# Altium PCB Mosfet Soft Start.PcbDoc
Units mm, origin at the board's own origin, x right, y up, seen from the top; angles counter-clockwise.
Board outline 50.5 x 33.6 mm, 2 copper layers (Top Layer, Bottom Layer), stack 1.64 mm thick; 46 components, 22 nets, 109 pads, 85 vias.
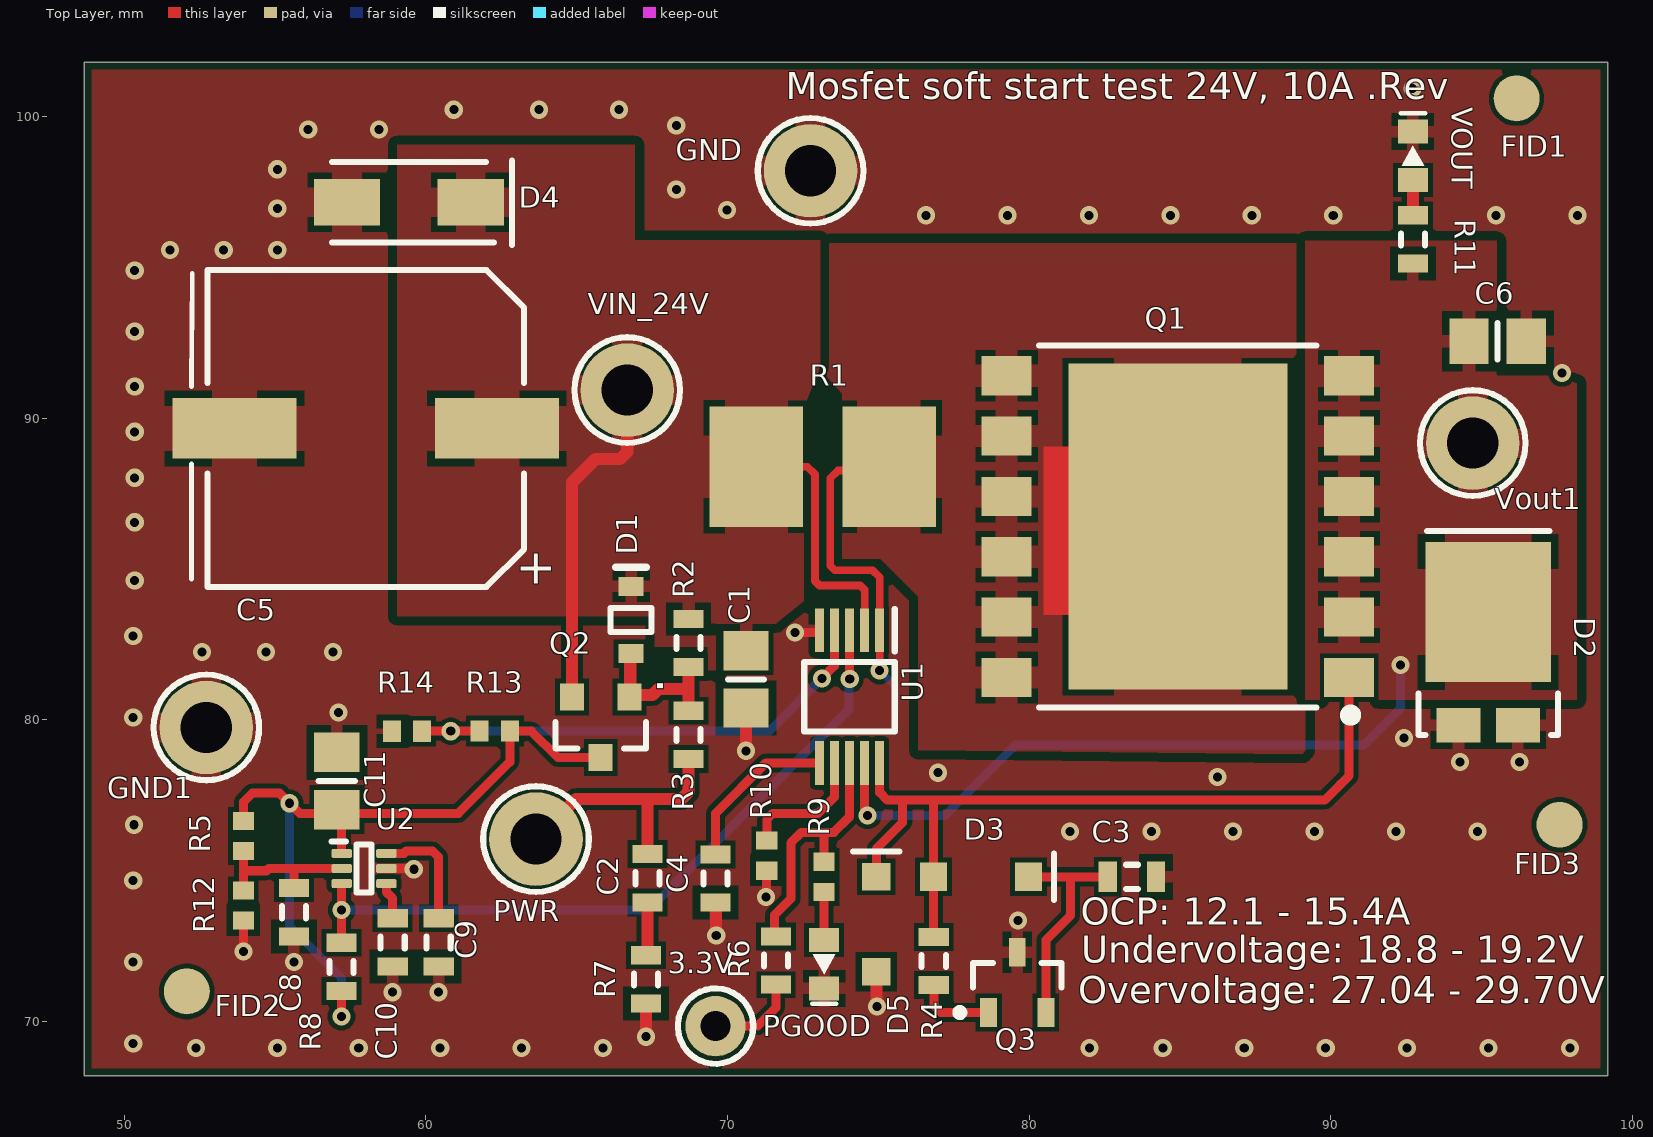
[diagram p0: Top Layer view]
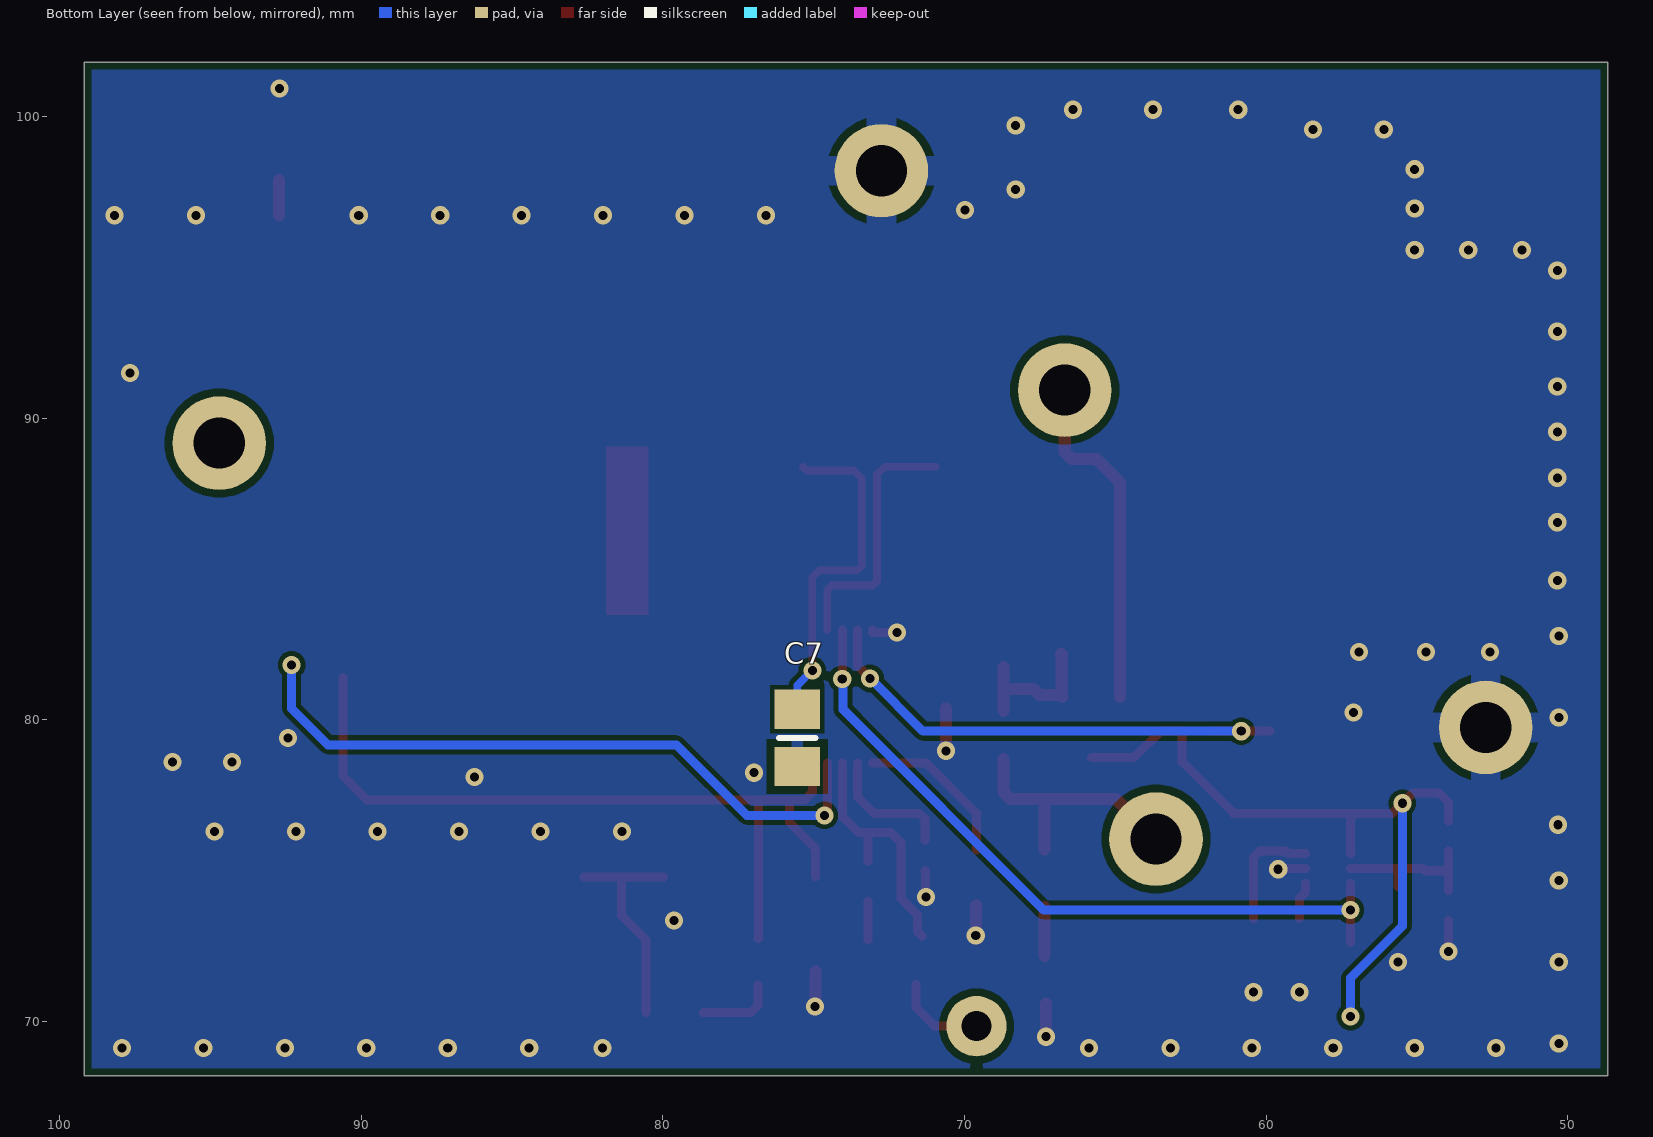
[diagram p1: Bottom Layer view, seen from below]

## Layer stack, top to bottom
Top Solder: solder mask 0.0102, Solder Resist, Dk 3.5
Top Layer: signal copper 0.07
Dielectric 1: dielectric 1.5, FR-4, Dk 4.8
Bottom Layer: signal copper 0.07
Bottom Solder: solder mask 0.0102, Solder Resist, Dk 3.5

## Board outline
48.675,68.2 99.175,68.2 99.175,101.8 48.675,101.8

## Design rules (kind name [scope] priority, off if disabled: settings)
BoardOutlineClearance [All] p1: gap=0.254 ignorepadtopadclearanceinfootprint=FALSE except(0: Arc-SplitContinuation Track-SplitContinuation SMDPad-SplitContinuation THPad-SplitContinuation Via-SplitContinuation Fill-SplitContinuation Poly-SplitContinuation Region-SplitContinuation Text-SplitContinuation; 0.05: Text-OutlineEdge)
Clearance "Clearance_MTG hole" [All vs (HasFootprint('M3 MOUNTING HOLE'))] p1: gap=0.152 ignorepadtopadclearanceinfootprint=TRUE except(0.25: THPad-Fill THPad-Poly THPad-Region Fill-Fill Fill-Poly Fill-Region Poly-Poly Poly-Region Region-Region; 0.4: SMDPad-Fill SMDPad-Poly SMDPad-Region)
Clearance [All] p2: gap=0.152 ignorepadtopadclearanceinfootprint=TRUE except(0.25: THPad-Fill THPad-Poly THPad-Region; 0.3: Fill-Fill Fill-Poly Fill-Region Poly-Poly Poly-Region Region-Region)
DiffPairsRouting DiffPairsRouting_1 [All] p1: maxlimit=0.254 minlimit=0.254 mostfreqgap=0.254 toplayer_minwidth=0.381 toplayer_maxwidth=0.381 toplayer_prefwidth=0.381 bottomlayer_minwidth=0.381 bottomlayer_maxwidth=0.381 bottomlayer_prefwidth=0.381 maxuncoupledlength=12.7
DiffPairsRouting [All] p2: maxlimit=0.254 minlimit=0.254 mostfreqgap=0.254 toplayer_minwidth=0.381 toplayer_maxwidth=0.381 toplayer_prefwidth=0.381 bottomlayer_minwidth=0.381 bottomlayer_maxwidth=0.381 bottomlayer_prefwidth=0.381 maxuncoupledlength=12.7
HoleSize [All] p1: absolutevalues=TRUE maxlimit=10 minlimit=0.2 maxpercent=80.000 minpercent=20.000
HoleToHoleClearance [All] p1: gap=0.3 allowstackedmicrovias=TRUE
MinimumSolderMaskSliver MinimumSolderMaskSliver_1 [All vs HasFootprint('FC2QFN')] p1: minsoldermaskwidth=0.01
MinimumSolderMaskSliver MinimumSolderMaskSliver_2 [All vs HasFootprint('DFN2020MD-6')] p2: minsoldermaskwidth=0.01
MinimumSolderMaskSliver [All] p3: minsoldermaskwidth=0.047
NetAntennae [All] p1: netantennaetolerance=0.8
PolygonConnect [All] p1: thpad.connectstyle=Relief thpad.reliefconductorwidth=0.6 thpad.reliefentries=4 thpad.polygonreliefangle="90 Angle" thpad.airgapwidth=0.2 smdpad.connectstyle=Relief smdpad.reliefconductorwidth=0.4 smdpad.reliefentries=4 smdpad.polygonreliefangle="90 Angle" smdpad.airgapwidth=0.2 via.connectstyle=Direct via.reliefconductorwidth=0.6 via.reliefentries=4 via.polygonreliefangle="90 Angle" via.airgapwidth=0.2
RoutingVias [All] p1: holewidth=0.2 width=0.45 viastyle="Through Hole" minholewidth=0.2 minwidth=0.4 maxholewidth=0.711 maxwidth=1.27
SilkToSilkClearance [All] p1: silktosilkclearance=0.01
SilkToSolderMaskClearance [IsPad] p1: minsilkscreentomaskgap=0.02 clearancetoexposedcopper=TRUE
SolderMaskExpansion [All] p1: expansion=0.102 istentingtop=FALSE
SupplyNets "Schematic Supply Nets" [InNet('+3.3V')] p1: voltage=0.000
SupplyNets "Schematic Supply Nets_9" [InNet('VIN_24V_SW')] p2: voltage=0.000
SupplyNets "Schematic Supply Nets_8" [InNet('Vin_24V')] p3: voltage=0.000
SupplyNets "Schematic Supply Nets_5" [InNet('GND')] p4: voltage=0.000
UnConnectedPin [All] p1 off:
UnRoutedNet [All] p1: checkbadconnections=TRUE
ViasUnderSMD [All] p1: allowed=FALSE
Width [All] p1: maxlimit=20 minlimit=0.152 preferedwidth=0.254
22 further rules are at their usual default settings.

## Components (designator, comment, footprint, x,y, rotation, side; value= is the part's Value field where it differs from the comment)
3.3V "TPAD6R" "TP - BLACK 1MM" 69.6,69.85 r0 top
C1 "1uF" 2012[0805] 70.612,81.341 r90 top
C2 "220nF" 1608(0603) 67.347,74.752 r270 top
C3 "3.3nF" 1608(0603) 83.4,74.8 r0 top
C4 "330nF" 1608(0603) 69.596,74.742 r270 top
C5 "100uF" FP-ZAG-MFG 58.007,89.662 r0 top
C6 "1uF" 2012[0805] 95.525,92.55 r180 top
C7 "1uF" 2012[0805] 75.541,79.404 r90 bottom
C8 "1nF" 1608(0603) 55.625,73.625 r270 top
C9 "0.33uF" 1608(0603) 60.425,72.625 r270 top
C10 "0.15uF" 1608(0603) 58.9,72.625 r270 top
C11 "1uF" 2012[0805] 57.05,77.975 r270 top
D1 "12V" SOD-323-3 66.802,83.312 r270 top value=24V
D2 "=Value" TO-277-3LD 95.21,82.575 r270 top
D3 "1N4148W-7-F" DIOD-SOD123-2_V 78.4,74.8 r0 top
D4 "24V" DIOM5127X229N 59.436,97.155 r180 top
D5 "36V" DIOD-SOD123-2_V 74.93,73.228 r90 top
FID1 "Fiducial" FID 96.15,100.6 r90 top
FID2 "Fiducial" FID 52.075,71 r90 top
FID3 "Fiducial" FID 97.575,76.525 r90 top
GND "TPAD6R" "TP - BLACK 1.5MM" 72.75,98.2 r0 top
GND1 "TPAD6R" "TP - BLACK 1.5MM" 52.725,79.75 r0 top
PGOOD "Power LED" "1608[0603]_LED Green" 73.2,71.9 r90 top value=Green
PWR "TPAD6R" "TP - BLACK 1.5MM" 63.65,76.05 r0 top
Q1 "PSMNR90-80ASEJ" CCPAK1212 84.923,86.407 r90 top
Q2 "" "FP-SOT23-MFG - PFET" 65.794,79.756 r270 top
Q3 "BJT NPN transistor" ONSC-SOT-23-3-318-08_V 79.6,71.3 r90 top
R1 "4mR" 2512_SENSE 73.152,88.392 r0 top
R2 "18K" 1608(0603) 68.707,82.55 r90 top
R3 "30K" 1608(0603) 68.707,79.502 r90 top
R4 "1K" 1608(0603) 76.835,72.009 r90 top
R5 "73.2K" 0402(1005) 53.95,76.15 r90 top
R6 "100K" 1608(0603) 71.6,72.025 r270 top
R7 "51R" 1608(0603) 67.3,71.4 r90 top
R8 "100K" 1608(0603) 57.2,71.815 r270 top
R9 "680R" 0402(1005) 73.2,74.8 r90 top
R10 "162K" 0402(1005) 71.3,75.5 r90 top
R11 "10K" 1608(0603) 92.712,95.925 r270 top
R12 "2.8K" 0402(1005) 53.95,73.85 r90 top
R13 "47.5K" 0402(1005) 62.284,79.629 r0 top
R14 "4.3K" 0402(1005) 59.375,79.625 r0 top
U1 "Soft start IC" VSSOP10 74.041,80.772 r270 top
U2 "Voltage supervisor. Resets for 1s when UVLO occurs" SOTFL50P160X60-6N 57.95,75.075 r0 top
VIN_24V "TPAD6R" "TP - BLACK 1.5MM" 66.675,90.932 r90 top
VOUT "Power LED" "1608[0603]_LED GREEN" 92.712,98.7 r270 top value=Green
Vout1 "TPAD6R" "TP - BLACK 1.5MM" 94.7,89.175 r90 top

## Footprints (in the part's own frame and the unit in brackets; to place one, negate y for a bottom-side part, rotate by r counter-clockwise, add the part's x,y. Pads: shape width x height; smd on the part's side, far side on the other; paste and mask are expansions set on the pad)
0402(1005) [mm] "Chip Resistor, Body 1.0x0.5mm, IPC Medium Density"
  rect 0.6x0.7 smd: 1(-0.5,0) 2(0.5,0)
  body extent -0.52,-0.27 0.53,0.28, height 0.4
1608(0603) [mm]
  rect 0.6x1 smd mask+0.076: 1(-0.8,0) 2(0.8,0)
  silkscreen extent -0.2,-0.4 0.2,0.4, body extent -0.8,-0.4 0.8,0.4, height 0.5
"1608[0603]_LED Green" [mm] "Chip Resistor; Body 1.1 x 0.8 mm (LxW)"
  rect 0.8x1 smd mask+0.076: A(0.8,0) K(-0.8,0)
  silkscreen extent -1.3,-0.4 0.33,0.4, body extent -0.81,-0.39 0.81,0.39, height 0.72
"1608[0603]_LED GREEN" [mm] "Chip Resistor; Body 1.1 x 0.8 mm (LxW)"
  rect 0.8x1 smd mask+0.076: A(0.8,0) K(-0.8,0)
  silkscreen extent -1.4,-0.39 0.33,0.41, body extent -0.81,-0.39 0.81,0.39, height 0.72
2012[0805] [mm]
  rect 1.3x1.5 smd: 1(-0.95,0) 2(0.95,0)
  silkscreen extent 0,-0.6 0,0.6, body extent -1.1,-0.7 1.1,0.7, height 0.6
2512_SENSE [mm] "Chip Resistor; Body 6.3 x 3.2 mm (LxW typ)"
  rect 3.1x4 smd: 1(-2.2,0) 2(2.2,0)
  body extent -3.22,-1.68 3.22,1.68, height 0.71
CCPAK1212 [mm]
  rect 1.3x1.65 smd paste-0.1: D(-5,5.675) D(-3,5.675) D(-1,5.675) D(1,5.675) D(3,5.675) D(5,5.675) G(-5,-5.675) S(-3,-5.675) S(-1,-5.675) S(1,-5.675) S(3,-5.675) S(5,-5.675)
  rect 10.8x7.26 smd paste-2539.97: D(0,0)
  silkscreen extent -6.3,-5.77 6,4.6, body extent -5.99,-6 6.01,6, height 2.5
DIOD-SOD123-2_V [mm] "SOD123, 2-Leads, Body 2.7x1.55mm, Height 1.45mm"
  rect 0.9x0.95 smd: A(-1.575,0) K(1.575,0)
  silkscreen extent 2.41,-0.77 2.41,0.77, body extent -1.35,-0.77 1.35,0.77, height 1.45
DIOM5127X229N [mm]
  rect 2.2x1.55 smd: 1(-2.05,0) 2(2.05,0)
  silkscreen extent -3.41,-1.38 2.55,1.42, body extent -2.61,-1.3 2.61,1.3, height 2.31
FID [mil]
  round 60 smd: 0(0,0)
"FP-SOT23-MFG - PFET" [mm]
  rect 0.9x0.8 smd paste+0: D(1,0) G(-1,0.95) S(-1,-0.95)
  silkscreen extent -0.18,-1.5 0.7,1.5, body extent -1.2,-1.45 1.2,1.45, height 1.1
FP-ZAG-MFG [mm]
  rect 4.1x2 smd paste+0 mask+0: +(4.35,0) -(-4.35,0)
  silkscreen extent -5.77,-5.25 5.25,5.25, body extent -6.65,-5.5 6.65,5.5, height 0.25
ONSC-SOT-23-3-318-08_V [mm] "SOT23, 3-Leads, Body 2.92x1.3mm, Pitch 0.95mm"
  rect 0.95x0.56 smd: 1(-1,0.95) 2(-1,-0.95) 3(1,0)
  silkscreen extent -1.12,-1.46 0.65,2.02, body extent -0.65,-1.46 0.65,1.46, height 1.11
SOD-323-3 [mm] "SOD, 2-Leads, Body 1.7x1.25mm"
  rect 0.63x0.83 smd: 1(-1.115,0) 2(1.115,0)
  silkscreen extent -1.75,-0.67 0.4,0.67, body extent -0.85,-0.63 0.85,0.63, height 1.06
SOTFL50P160X60-6N [mm]
  rrect33% 0.67x0.3 smd mask+0.05: 1(-0.74,0.5) 2(-0.74,0) 3(-0.74,-0.5) 4(0.74,-0.5) 5(0.74,0) 6(0.74,0.5)
  silkscreen extent -1.07,-0.8 0.25,0.9, body extent -0.8,-0.8 0.8,0.8, height 0.6
TO-277-3LD [mm]
  rect 1.15x1.45 smd paste+0 mask+0: A(2.75,0.985) A(2.75,-0.985)
  rect 4.65x4.15 smd paste+0 mask+0: K(-1,0)
  silkscreen extent -3.68,-2.31 3.08,2.31, body extent -3.42,-2.41 3.42,2.41, height 0.25
"TP - BLACK 1.5MM" [mm] "Test Point - Black - 1mm Hole"
  round 3.1 hole 1.7: 1(0,0)
  silkscreen extent -1.75,-1.75 1.75,1.75
"TP - BLACK 1MM" [mm] "Test Point - Black - 1mm Hole"
  round 2 hole 1: 1(0,0)
  silkscreen extent -1.25,-1.25 1.25,1.25
VSSOP10 [mm] "R-PDSO-G8, SOT765-1"
  rrect5% 1.45x0.3 smd: 1(-2.2,1) 2(-2.2,0.5) 3(-2.2,0) 4(-2.2,-0.5) 5(-2.2,-1) 6(2.2,-1) 7(2.2,-0.5) 8(2.2,0) 9(2.2,0.5) 10(2.2,1)
  silkscreen extent -2.9,-1.5 1.15,1.5, body extent -2.46,-1.5 2.46,1.5, height 1.11

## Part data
3.3V GND GND1 PWR VIN_24V Vout1: library part "Test Pad 0.6mm", "0.6mm round"
C1 C6 C7 C11: library part CAPNP, "CAP CER 1UF 100V X7S 0805", Case/Package=0805, Manufacturer="Murata Electronics", Manufacturer Part Number=GRJ21BC72A105KE11L, Rating=100V, Temperature Coefficient=X7S, Tolerance=±10%
C2 C4: library part CAPNP, "Multilayer Ceramic Capacitors MLCC - SMD/SMT SOFT 0603 50V 0.22uF X7R 10% AEC-Q200", Case/Package=0603, Manufacturer=KEMET, Manufacturer Part Number=CGA3E3X7R1H224K080AE, Rating=50V, Temperature Coefficient=X7R
C3: library part CAPNP, "CAP CER 3300PF 50V C0G/NP0 0603", Case/Package=0603, Manufacturer=KEMET, Manufacturer Part Number=C0603X332J5GACAUTO, Rating=50V, Temperature Coefficient="C0G, NP0"
C5: library part "CAP ALUM POLY HYB 100uF 50V SMD", "Cap Aluminum 100uF 50V 20% (10 X 10.2mm) SMD 0.028 Ohm 2000mA 5000 hr 105°C Embossed T/R", Case/Package=SMD, Manufacturer=Panasonic, Manufacturer Part Number=EEH-ZA1H101P, Rating=50V
C8: library part CAPNP, "CAP CER 0603 1NF 50V X7R 10%", Case/Package=0603, Manufacturer=KEMET, Manufacturer Part Number=C0603X102K5RAC3316, Rating=50V, Temperature Coefficient=X7R, Tolerance=±10%
C9: library part CAPNP, "CAP CER 0.33UF 25V X8R 0603", Case/Package=0603, Manufacturer="TDK Corporation", Manufacturer Part Number=C1608X8R1E334K080AE, Rating=25V, Temperature Coefficient=X7R, Tolerance=±10%
C10: library part CAPNP, "CAP CER 0.15UF 50V X7R 0603", Case/Package=0603, Manufacturer=KEMET, Manufacturer Part Number=C0603X154J5RECAUTO, Rating=50V, Temperature Coefficient=X7R, Tolerance=±5%
D1: library part SMA6J24A-Q, "TVS Diode (Uni-directional)", Case/Package=SOD-323F, Manufacturer=onsemi, Manufacturer Part Number=MM3Z12VB
D2: library part Schottky, "Schottky Diodes & Rectifiers 15A 50V Schottky Rectifier", Case/Package=TO-277-3, Manufacturer=onsemi, Manufacturer Part Number=FSV1550V, Rating=15A, Voltage - DC Reverse (Vr) (Max)=50V
D3: library part "D 100V 20A", "SURFACE-MOUNT FAST SWITCHING DIODE", Case/Package=SOD-123, Manufacturer=Diodes, Rating=300mA
D4: library part SMA6J24A-Q, "TVS Diode (Uni-directional)", Case/Package=DO-214AC-2, Manufacturer=Bourns
D5: library part SMA6J24A-Q, "TVS Diode (Uni-directional)", Case/Package=SOD123, Manufacturer="Diodes Incorporated", Manufacturer Part Number=DDZ36S-7
FID1 FID2 FID3: library part PCB_FIDUCIAL, "PCB FIDUCIAL"
PGOOD VOUT: library part LED0, "Green 574nm LED Indication - Discrete 1.9V 0603 (1608 Metric)", Case/Package=0603, Colour=GREEN, Manufacturer=Bivar, Manufacturer Part Number=SM0603GCL, Voltage Forward @ If="1.9V @ 2mA"
Q1: library part PSMNR90-80ASE, "N-channel, 80 V, 0.9 mOhm, MOSFET with enhanced SOA in / CCPAK1212 package", Case/Package=CCPAK1212, Manufacturer=Nexperia, Rating="495A, 80V"
Q2: library part DMP6023LE, "P-Channel 30 V 4.3A (Ta) 1.38W (Ta) Surface Mount SOT-23-3", Case/Package=SOT23, Manufacturer="Diodes Incorporated", Manufacturer Part Number=DMP3056L-7
Q3: library part CMP-1048-00557-1, "Bipolar Transistors - BJT SS HV XSTR PNP 150V", Case/Package=SOT-23-3, Manufacturer="On Semiconductor", Manufacturer Part Number=MMBT5401LT1G
R1: library part Res3, "RES 0.004 OHM 1% 3W 2512", Case/Package=2512, Manufacturer="Bourns Inc.", Manufacturer Part Number=CRE2512-FZ-R004E-3, Rating=3W, Tolerance=1%
R2: library part "RES 0R 1% 0603", "RES 18K OHM 1% 1/10W 0603", Case/Package=0603, Manufacturer=YAGEO, Manufacturer Part Number=RC0603FR-0718KL, Tolerance=1%
R3: library part "RES 0R 1% 0603", "RES 30K OHM 1% 1/10W 0603", Case/Package=0603, Manufacturer="Stackpole Electronics Inc", Manufacturer Part Number=RMCF0603FT30K0, Tolerance=1%
R4: library part "RES 1K 1% 0603", "RES 1K OHM 1% 1/8W 0603 Thin Film", Case/Package=0603, Manufacturer=Panasonic, Manufacturer Part Number="Stackpole Electronics Inc", Tolerance=1%
R5: library part "RES 1K 1% 0402", "RES 73.2K OHM 0.1% 0.13W 0402", Case/Package=0402, Manufacturer="Panasonic Electronic Components", Manufacturer Part Number=TNPW040273K2BEED, Tolerance=0.1%
R6: library part "RES 100K 1% 0603", "RES SMD 100K OHM 0.1% 1/10W 0603 Thin Film", Case/Package=0603, Manufacturer=Susumu, Manufacturer Part Number=RG1608P-104-B-T5, Tolerance=0.1%
R7: library part "RES 0R 1% 0603", "RES 51 OHM 1% 1/10W 0603", Case/Package=0603, Manufacturer="Stackpole Electronics Inc", Manufacturer Part Number=RMCF0603FT51R0, Tolerance=1%
R8: library part "RES 0R 1% 0603", "RES 100K OHM 1% 1/10W 0603", Case/Package=0603, Manufacturer=YAGEO, Manufacturer Part Number=RC0603FR-07100KL, Tolerance=1%
R9: library part "RES 1K 1% 0402", "RES SMD 680 OHM 1% 1/16W 0402 Thin Film", Case/Package=0402, Manufacturer=YAGEO, Manufacturer Part Number=RT0402FRE07680RL, Tolerance=1%
R10: library part "RES 1K 1% 0402", "RES 162K OHM 0.1% 1/10W 0402 Thin Film", Case/Package=0402, Manufacturer="TE Connectivity Passive Product", Manufacturer Part Number=RP73PF1E162KBTD, Tolerance=0.1%
R11: library part "RES 10K 1% 0603", "Res Thick Film 0603 10K Ohm 1% 1/10W ±100ppm/°C Molded SMD Punched Carrier T/R", Case/Package=0603, Manufacturer=Panasonic, Manufacturer Part Number=ERJ-3EKF1002V, Tolerance=1%
R12: library part "RES 1K 1% 0402", "RES SMD 2.8K OHM 0.1% 1/16W 0402", Case/Package=0402, Manufacturer="Panasonic Electronic Components", Manufacturer Part Number=RG1005P-2801-B-T5, Tolerance=0.1%
R13: library part "RES 1K 1% 0402", "RES SMD 47.5KOHM 0.1% 1/16W 0402", Case/Package=0402, Manufacturer="Panasonic Electronic Components", Manufacturer Part Number=ERA-2AEB4752X, Tolerance=0.1%
R14: library part "RES 1K 1% 0402", "RES SMD 4.3K OHM 0.1% 1/16W 0402", Case/Package=0402, Manufacturer="Panasonic Electronic Components", Manufacturer Part Number=ERA-2AEB432X, Tolerance=0.1%
U1: library part LM5069, "Positive High Voltage Hot Swap / Inrush Current Controller with Power Limiting, 10-pin MSOP, Pb-Free", Case/Package=VSSOP10, Current limit="Current limit: 12A", Manufacturer="Texas Instruments", Manufacturer Part Number=LM5069MM-2/NOPB
U2: library part TPS3842A011DRLRQ1, "Supervisor Open Drain or Open Collector 1 Channel SOT-563", Case/Package=SOT-5X3, Manufacturer="Texas Instruments", Manufacturer Part Number=TPS3842A011DRLR

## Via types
v1: diameter 0.6, hole 0.3, Top Layer to Bottom Layer, 79 vias
v2: diameter 0.6, hole 0.3, Top Layer to Bottom Layer, tented both sides, 3 vias
v3: diameter 0.6, hole 0.3, Top Layer to Bottom Layer, tented top, 3 vias

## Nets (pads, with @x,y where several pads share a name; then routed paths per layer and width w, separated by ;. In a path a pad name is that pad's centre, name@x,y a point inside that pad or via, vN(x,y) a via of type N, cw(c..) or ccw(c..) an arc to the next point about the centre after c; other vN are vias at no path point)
+3.3V: 3.3V.1 R6.2 | length 3
  Top Layer w0.3: 3.3V.1 70.988,69.85 71.6,70.462 R6.2
\C\H\G\_\F\L\T\: R6.1 R9.2 U1.8 | length 8.5
  Top Layer w0.3: R6.1@71.4,72.825 71.402,72.825 71.552,72.975 71.552,73.527 72.1,74.075 72.1,75.925 72.45,76.275 73.26,76.275 ; R9.2 73.2,76.215 73.26,76.275 ; U1.8 74.041,76.791 73.525,76.275 73.26,76.275
GND: C1.1 C3.2 C4.2 C5.- C6.1 C7.1 C8.2 C9.2 C10.2 C11.1 D2.A D4.2 D5.A GND1.1 GND.1 PGOOD.K Q3.3 R7.1 R10.1 R12.1 R14.1 U1.5 U2.5 VOUT.K | length 8.4
  Top Layer w0.3: v1(53.95,72.325) R12.1 ; U2.5 59.575,75.075 v1(59.6,75.05) ; v2(71.275,74.125) 71.288,74.137 71.288,74.988 R10.1 ; v2(72.241,82.896) 73.041,82.896 U1.5
  Top Layer w0.4: v1(67.3,69.5) R7.1 ; C4.2@69.596,73.842 69.611,73.842 69.611,72.864 v1(69.625,72.85) ; v1(70.612,78.977) C1.1 ; D5.A 74.94,71.643 74.94,70.51 v1(74.95,70.5)
  other v1: 52.375,69.125 55.075,69.125 57.775,69.125 60.475,69.125 63.175,69.125 65.875,69.125 82,69.125 84.425,69.125 87.125,69.125 89.825,69.125 92.525,69.125 95.225,69.125 97.925,69.125 50.3,69.275 58.9,70.975 60.425,70.975 50.3,71.975 55.625,71.975 50.3,74.675 81.35,76.3 84.05,76.3 86.75,76.3 89.45,76.3 92.15,76.3 94.85,76.3 50.325,76.525 86.233,78.105 76.975,78.25 94.28,78.6 96.25,78.6 92.423,79.407 50.3,80.075 57.1,80.25 52.575,82.25 54.7,82.25 56.925,82.25 50.3,82.775 50.35,84.625 50.35,86.55 50.35,88.025 50.35,89.55 50.35,91.05 97.65,91.5 50.35,92.875 50.35,94.9 51.525,95.575 53.3,95.575 55.075,95.575 76.575,96.725 79.275,96.725 81.975,96.725 84.675,96.725 87.375,96.725 90.075,96.725 95.475,96.725 98.175,96.725 69.975,96.9 55.075,96.95 68.3,97.575 55.075,98.25 56.1,99.575 58.45,99.575 68.3,99.7 60.925,100.225 63.75,100.225 66.4,100.225 92.7,100.925
  other v2: 79.625,73.35
NetC2_2: C2.2 R7.2 | length 1.6
  Top Layer w0.4: R7.2@67.347,72.174 C2.2@67.347,73.802
NetC3_1: C3.1 D3.K Q3.2 | length 7.5
  Top Layer w0.3: D3.K 81.369,74.8 ; Q3.2 80.55,72.7 81.369,73.519 81.369,74.8 ; C3.1 81.369,74.8
NetC4_1: C4.1 U1.6 | length 5.3
  Top Layer w0.3: C4.1@69.596,75.692 69.596,76.896 71.272,78.572 U1.6
NetC7_2: C7.2 Q1.D R1.2 U1.1 | length 11.4
  Top Layer w0.254: v3(75.041,81.641) U1.1 75.041,84.725 74.803,84.963 73.555,84.963 73.406,85.112 73.406,88.011 73.66,88.265 75.225,88.265 R1.2
  Bottom Layer w0.254: v3(75.041,81.641) 75.541,81.141 C7.2
NetC8_1: C8.1 R5.1 R12.2 U2.2 | length 5.2
  Top Layer w0.3: R12.2 53.95,75 ; R5.1 53.95,75 ; C8.1@55.625,74.475 55.625,75.075 ; U2.2 55.625,75.075 ; 53.95,75 54.725,75 54.8,75.075 55.625,75.075
NetC9_1: C9.1 U2.6 | length 3.9
  Top Layer w0.3: U2.6 59.273,75.575 59.35,75.652 60.223,75.652 60.425,75.45 C9.1
NetC10_1: C10.1 U2.4 | length 1.2
  Top Layer w0.3: U2.4 58.69,74.296 58.9,74.086 C10.1
NetC11_2: C11.2 Q2.D R5.2 R8.2 R13.2 U2.1 | length 25
  Top Layer w0.3: R5.2 53.95,77.275 54.25,77.575 55.149,77.575 v1(55.486,77.238) 55.824,76.9 C11.2@57.05,76.9 ; U2.1@57.189,75.575 U2.1 57.21,76.74 C11.2@57.05,76.9 ; v1(57.2,70.165) R8.2 ; Q2.D 64.373,78.756 63.5,79.629 R13.2 62.784,78.609 61.075,76.9 C11.2@57.05,76.9
  Bottom Layer w0.3: v1(55.486,77.238) 55.486,73.164 57.2,71.45 v1(57.2,70.165)
NetD1_2: D1.2 Q2.G R2.1 R3.2 | length 5
  Top Layer w0.4: Q2.G Q2.G@66.76,80.772 ; D1.2 66.773,82.168 66.773,80.785 Q2.G@66.76,80.772 ; R3.2 68.707,81.026 ; R2.1 68.707,81.026 ; Q2.G@66.76,80.772 66.813,80.825 67.51,80.825 67.711,81.026 68.707,81.026
NetD3_A: D3.A D5.K Q1.G R4.2 U1.10 | length 27.7
  Top Layer w0.3: D5.K 74.93,75.73 75.805,76.605 75.805,77.334 75.796,77.343 ; U1.10 75.041,77.597 75.295,77.343 75.796,77.343 ; R4.2@76.835,72.759 76.83,72.764 76.83,74.795 D3.A 76.825,77.333 76.835,77.343 ; Q1.G 90.598,78.152 90.321,77.875 89.789,77.343 76.835,77.343 ; 75.796,77.343 76.835,77.343
NetPGOOD_A: PGOOD.A R9.1 | length 1.3
  Top Layer w0.3: PGOOD.A R9.1@73.2,74
NetQ3_1: Q3.1 R4.1 | length 2.6
  Top Layer w0.3: R4.1 76.835,70.54 77.075,70.3 Q3.1
NetR8_1: R8.1 U1.3 U2.3 | length 25.2
  Top Layer w0.3: R8.1 57.21,72.625 v1(57.21,73.696) U2.3 ; v1@57.2,73.475 v1@57.21,73.485 ; U1.3 74.041,81.584 74.05,81.575 v3(74.05,81.35)
  Bottom Layer w0.3: v1(57.21,73.696) 67.371,73.696 74.025,80.35 ; 73.304,79.629 74.025,80.35 ; v3(74.05,81.35) 74.025,81.325 74.025,80.35
NetR10_2: R10.2 U1.7 | length 4.4
  Top Layer w0.3: R10.2 71.3,76.7 71.5,76.9 73,76.9 73.541,77.441 U1.7
NetR11_1: R11.1 VOUT.A | length 1.2
  Top Layer w0.4: R11.1 VOUT.A
NetR13_1: R13.1 R14.2 U1.4 | length 16.7
  Top Layer w0.3: R14.2 59.877,79.627 61.782,79.627 R13.1 ; v3(73.125,81.375) 73.541,81.791 U1.4
  Bottom Layer w0.3: v1(60.825,79.625) 71.375,79.625 v3(73.125,81.375)
PWR: C2.1 PWR.1 R3.1 | length 8.5
  Top Layer w0.4: PWR.1 64.979,77.379 67.347,77.379 ; C2.1@67.347,75.702 67.347,77.368 67.358,77.378 68.473,77.378 68.707,77.613 R3.1
Vin_24V: C1.2 C5.+ D1.1 D4.1 Q2.S R1.1 R2.2 U1.2 VIN_24V.1 | length 20.1
  Top Layer w0.254: R1.1 72.644,88.392 72.898,88.138 72.898,84.604 73.047,84.455 74.4,84.455 74.549,84.306 74.549,82.972 U1.2
  Top Layer w0.4: Q2.S 64.844,87.869 65.621,88.646 66.441,88.646 66.675,88.88 VIN_24V.1
VIN_24V_SW: C6.2 D2.K Q1.S R11.2 U1.9 Vout1.1 | length 22.3
  Top Layer w0.3: U1.9 74.541,77.022 74.643,76.919 v1(74.643,76.838)
  Bottom Layer w0.3: v1(74.643,76.838) 77.213,76.838 79.55,79.175 91.1,79.175 92.299,80.374 v1(92.299,81.826)
pads on no net: FID1.0 FID2.0 FID3.0

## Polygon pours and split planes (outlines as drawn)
GND on Top Layer "GND_L01_P007" (solid, remove dead copper, pour order 7): 48.675,101.8 48.675,68.2 99.175,68.2 99.175,101.8
NetC7_2 on Top Layer "NETC7_2_L01_P003" (solid, remove dead copper, pour order 3): 73.303,95.8 73.303,91.351 73.802,90.809 73.802,85.344 75.057,85.344 76.327,84.074 76.327,78.994 89.154,78.868 89.154,95.8
VIN_24V_SW on Top Layer "VIN_24V_SW_L01_P000" (solid, remove dead copper, pour order 0): 89.154,80.675 98.15,80.675 98.15,91.4 95.5,91.4 95.5,95.885 89.154,95.885
Vin_24V on Top Layer "VIN_24V_L01_P002" (solid, remove dead copper, pour order 2): 59.055,99.06 66.929,99.06 66.929,95.901 73.064,95.901 73.064,91.718 72.517,90.313 72.523,83.937 71.625,83.214 71.625,81.651 69.342,81.651 69.342,82.423 67.591,82.423 67.591,83.439 59.055,83.439
GND on Bottom Layer "GND_L02_P005" (solid, remove dead copper, pour order 5): 48.675,101.8 48.675,68.2 99.175,68.2 99.175,101.8

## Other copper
Top Layer:
  rectangle net NetC7_2: 80.475,83.475 81.872,89.063

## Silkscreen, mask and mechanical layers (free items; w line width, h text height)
Top Overlay:
  text "Mosfet soft start test 24V, 10A .Rev" at 71.925,100.268 h1.52
  text "OCP: 12.1 - 15.4A" at 81.7,72.914 h1.52
  text "Undervoltage: 18.8 - 19.2V" at 81.72,71.66 h1.52
  text "Overvoltage: 27.04 - 29.70V" at 81.625,70.313 h1.52
Board Shape:
  the board outline again, w0.254
Drill Drawing:
  drawing of 216 lines, arcs and shapes, not listed
  text "Layer Map and Build Info" at 134.525,156.55 h1.5
  text "Stackup is for PCBway 2-layer 2oz standard stack-up" at 134.975,152.8 h1.5
  text "Layer" at 136.618,147.314 h1.52
  text "Name" at 147.03,147.314 h1.52
  text "Material" at 170.646,147.314 h1.52
  text "Thickness" at 192.484,147.314 h1.52
  text "Constant" at 208.99,147.314 h1.52
  text "Board Layer Stack" at 223.464,147.314 h1.52
  text "Top Overlay" at 147.03,144.266 h1.52
  text "Top Solder" at 147.03,141.218 h1.52
  text "Solder Resist" at 170.646,141.218 h1.52
  text "0.010mm" at 192.484,141.218 h1.52
  text "3.5" at 208.99,141.218 h1.52
  text "1" at 136.618,138.17 h1.52
  text "Top Layer" at 147.03,138.17 h1.52
  text "0.070mm" at 192.484,138.17 h1.52
  text "Dielectric 1" at 147.03,135.122 h1.52
  text "FR-4" at 170.646,135.122 h1.52
  text "1.500mm" at 192.484,135.122 h1.52
  text "4.8" at 208.99,135.122 h1.52
  text "2" at 136.618,132.074 h1.52
  text "Bottom Layer" at 147.03,132.074 h1.52
  text "0.070mm" at 192.484,132.074 h1.52
  text "Bottom Solder" at 147.03,129.026 h1.52
  text "Solder Resist" at 170.646,129.026 h1.52
  text "0.010mm" at 192.484,129.026 h1.52
  text "3.5" at 208.99,129.026 h1.52
  text "Bottom Overlay" at 147.03,125.978 h1.52
  text "Material FR4 to IPC4101/99 or later" at 134.954,120.922 h1.5
  text "2oz copper" at 134.875,117.725 h1.5
  text "Total thickness target" at 134.354,112.797 h1.5
  text "inc. plating 1.6mm +/-10%" at 134.354,109.797 h1.5
  text "Surface Finish:" at 134.354,104.797 h1.5
  text "Immersion Gold Ni 3-5um, Au  (2U'')" at 134.354,101.797 h1.5
  text "Solder Resist:" at 134.354,96.797 h1.5
  text "Photoimageable over bare copper" at 134.354,93.797 h1.5
  text "Green on both sides" at 134.354,90.797 h1.5
  text "Silkscreen:" at 134.354,85.797 h1.5
  text "White on both sides" at 134.354,82.797 h1.5
  text "No changes to be made to this data without permission" at 133.879,77.297 h1.5
  text "Bare Board Test" at 134.031,73.225 h1.5
  text "Manufacture in accordance with specification BS EN 60249-2-4/ IPC-A-600 CLASS2" at 133.879,69.297 h1.5
  text "PCB to be ROHS compliant" at 133.879,66.297 h1.5
  text "Drill Table (Holes are finished size after plating)" at 133.779,62.472 h1.5
  text "Symbol" at 134.902,60.123 h1.83
  text "Count" at 147.751,60.123 h1.83
  text "Hole Size" at 161.209,60.123 h1.83
  text "Plated" at 188.887,60.123 h1.83
  text "Hole Type" at 201.736,60.123 h1.83
  text "Drill Layer Pair" at 220.375,60.123 h1.83
  text "Via/Pad" at 258.464,60.123 h1.83
  text "Pad Shape" at 273.446,60.123 h1.83
  text "Template" at 292.389,60.123 h1.83
  text "Description" at 323.368,60.123 h1.83
  text "Hole Tolerance (+)" at 345.054,60.123 h1.83
  text "Hole Tolerance (-)" at 378.927,60.123 h1.83
  text "1" at 147.751,56.313 h1.52
  text "1.000mm (39.37mil)" at 161.209,56.313 h1.52
  text "PTH" at 188.887,56.313 h1.52
  text "Round" at 201.736,56.313 h1.52
  text "Top Layer - Bottom Layer" at 220.375,56.313 h1.52
  text "Pad" at 258.464,56.313 h1.52
  text "Rounded" at 273.446,56.313 h1.52
  text "c200h100_2690082004" at 292.389,56.313 h1.52
  text "5" at 147.751,52.503 h1.52
  text "1.700mm (66.93mil)" at 161.209,52.503 h1.52
  text "PTH" at 188.887,52.503 h1.52
  text "Round" at 201.736,52.503 h1.52
  text "Top Layer - Bottom Layer" at 220.375,52.503 h1.52
  text "Pad" at 258.464,52.503 h1.52
  text "Rounded" at 273.446,52.503 h1.52
  text "c310h170_2690082004" at 292.389,52.503 h1.52
  text "85" at 147.751,48.693 h1.52
  text "0.300mm (11.81mil)" at 161.209,48.693 h1.52
  text "PTH" at 188.887,48.693 h1.52
  text "Round" at 201.736,48.693 h1.52
  text "Top Layer - Bottom Layer" at 220.375,48.693 h1.52
  text "Via" at 258.464,48.693 h1.52
  text "Rounded" at 273.446,48.693 h1.52
  text "(Mixed)" at 292.389,48.693 h1.52
  text "91 Total" at 147.751,44.883 h1.52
